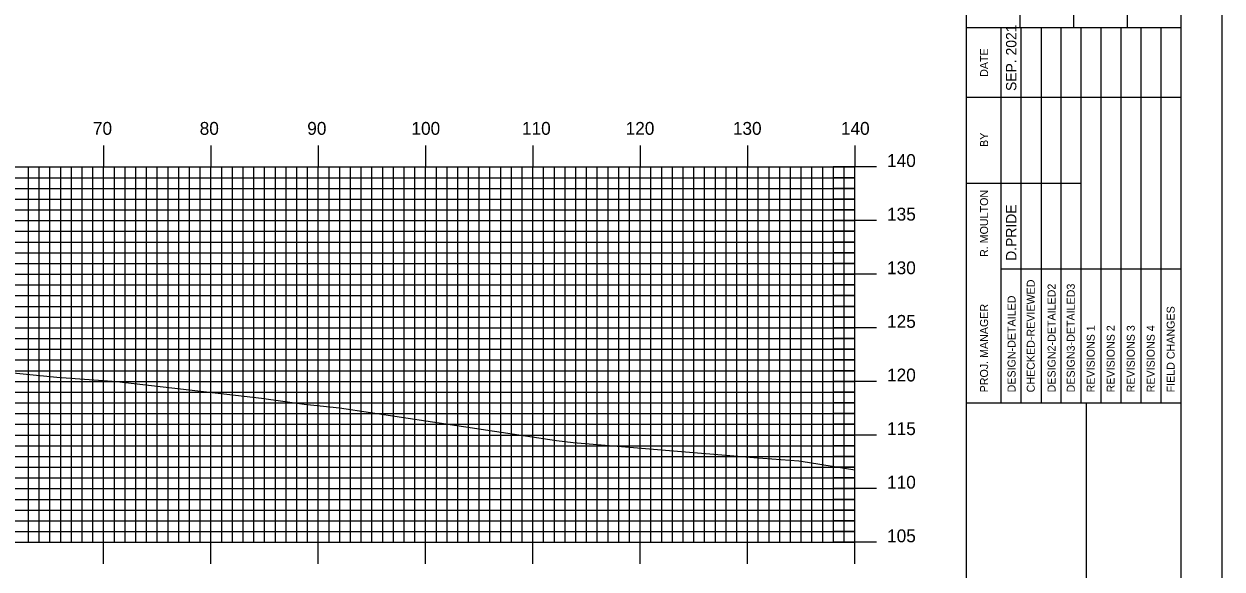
# Model space of a CAD drawing. Extents: x 1785402 to 1785745, y 442591 to 442811.
# Drawn here: x 1785630.1 to 1785741.8, y 442671.2 to 442722 of the extents above; entities that cross this region are included whole.
import ezdxf

# ---------------------------------------------------------------- set-up
doc = ezdxf.new("R2010")
doc.units = 0
for name, color, linetype in [('BORDER', 7, 'Continuous'), ('H_V ANNOTATION', 7, 'Continuous'), ('MAJOR', 7, 'Continuous'), ('MINOR', 7, 'Continuous'), ('PLOT BOUNDARY', 7, 'Continuous'), ('S_Roadway_Centerline', 7, 'Continuous')]:
    doc.layers.add(name, color=color, linetype=linetype)

msp = doc.modelspace()

# ---------------------------------------------------------------- linework, layer by layer
at = {"layer": 'BORDER'}
for p, q in [((1785717.94, 442596.67), (1785717.94, 442806.67)), ((1785722.94, 442721.67), (1785722.94, 442738.97)), ((1785722.94, 442721.67), (1785722.94, 442738.97)), ((1785727.94, 442721.67), (1785727.94, 442738.97)), ((1785727.94, 442721.67), (1785727.94, 442738.97)), ((1785732.94, 442721.67), (1785732.94, 442738.97)), ((1785732.94, 442721.67), (1785732.94, 442738.97)), ((1785717.94, 442721.67), (1785737.94, 442721.67)), ((1785717.94, 442721.67), (1785737.94, 442721.67)), ((1785717.94, 442686.67), (1785737.94, 442686.67)), ((1785717.94, 442686.67), (1785737.94, 442686.67)), ((1785729.12, 442616.67), (1785729.12, 442686.67)), ((1785729.12, 442616.67), (1785729.12, 442686.67))]:
    msp.add_line(p, q, dxfattribs=at)
msp.add_lwpolyline([(1785417.94, 442596.67), (1785737.94, 442596.67), (1785737.94, 442806.67), (1785417.94, 442806.67)], close=True, dxfattribs=at)
for points in [[(1785721.17, 442715.17), (1785721.17, 442721.67)], [(1785721.17, 442715.17), (1785721.17, 442721.67)], [(1785723.03, 442686.68), (1785723.03, 442721.67)], [(1785723.03, 442686.68), (1785723.03, 442721.67)], [(1785724.9, 442721.67), (1785724.9, 442686.68)], [(1785724.9, 442721.67), (1785724.9, 442686.68)], [(1785726.76, 442686.68), (1785726.76, 442721.67)], [(1785726.76, 442686.68), (1785726.76, 442721.67)], [(1785728.62, 442686.68), (1785728.62, 442721.67)], [(1785728.62, 442686.68), (1785728.62, 442721.67)], [(1785730.49, 442686.68), (1785730.49, 442721.67)], [(1785730.49, 442686.68), (1785730.49, 442721.67)], [(1785732.35, 442686.68), (1785732.35, 442721.67)], [(1785732.35, 442686.68), (1785732.35, 442721.67)], [(1785734.21, 442686.68), (1785734.21, 442721.67)], [(1785734.21, 442686.68), (1785734.21, 442721.67)], [(1785736.08, 442686.68), (1785736.08, 442721.67)], [(1785736.08, 442686.68), (1785736.08, 442721.67)], [(1785721.17, 442686.68), (1785721.17, 442720.26)], [(1785721.17, 442686.68), (1785721.17, 442720.26)], [(1785717.94, 442715.17), (1785737.94, 442715.17)], [(1785717.94, 442715.17), (1785737.94, 442715.17)], [(1785717.94, 442707.17), (1785721.17, 442707.17)], [(1785717.94, 442707.17), (1785721.17, 442707.17)], [(1785721.17, 442707.17), (1785728.62, 442707.17)], [(1785721.17, 442707.17), (1785728.62, 442707.17)], [(1785721.17, 442699.17), (1785737.94, 442699.17)], [(1785721.17, 442699.17), (1785737.94, 442699.17)]]:
    msp.add_lwpolyline(points, dxfattribs=at)
at = {"layer": 'MAJOR'}
for p, q in [((1785637.54, 442710.67), (1785637.54, 442708.67)), ((1785647.54, 442710.67), (1785647.54, 442708.67)), ((1785657.54, 442710.67), (1785657.54, 442708.67)), ((1785667.54, 442710.67), (1785667.54, 442708.67)), ((1785677.54, 442710.67), (1785677.54, 442708.67)), ((1785687.54, 442710.67), (1785687.54, 442708.67)), ((1785697.54, 442710.67), (1785697.54, 442708.67)), ((1785707.54, 442710.67), (1785707.54, 442708.67)), ((1785427.54, 442708.67), (1785707.54, 442708.67)), ((1785427.54, 442708.67), (1785707.54, 442708.67)), ((1785637.54, 442673.67), (1785637.54, 442708.67)), ((1785647.54, 442673.67), (1785647.54, 442708.67)), ((1785657.54, 442673.67), (1785657.54, 442708.67)), ((1785667.54, 442673.67), (1785667.54, 442708.67)), ((1785677.54, 442673.67), (1785677.54, 442708.67)), ((1785687.54, 442673.67), (1785687.54, 442708.67)), ((1785697.54, 442673.67), (1785697.54, 442708.67)), ((1785709.54, 442708.67), (1785705.53, 442708.67)), ((1785707.54, 442673.67), (1785707.54, 442708.67)), ((1785707.54, 442673.67), (1785707.54, 442708.67)), ((1785427.54, 442703.67), (1785707.54, 442703.67)), ((1785709.54, 442703.67), (1785705.53, 442703.67)), ((1785427.54, 442698.67), (1785707.54, 442698.67)), ((1785709.54, 442698.67), (1785705.53, 442698.67)), ((1785427.54, 442693.67), (1785707.54, 442693.67)), ((1785709.54, 442693.67), (1785705.53, 442693.67)), ((1785427.54, 442688.67), (1785707.54, 442688.67)), ((1785709.54, 442688.67), (1785705.53, 442688.67)), ((1785427.54, 442683.67), (1785707.54, 442683.67)), ((1785709.54, 442683.67), (1785705.53, 442683.67)), ((1785427.54, 442678.67), (1785707.54, 442678.67)), ((1785709.54, 442678.67), (1785705.53, 442678.67)), ((1785427.54, 442673.67), (1785707.54, 442673.67)), ((1785427.54, 442673.67), (1785707.54, 442673.67)), ((1785637.54, 442671.66), (1785637.54, 442673.67)), ((1785647.54, 442671.66), (1785647.54, 442673.67)), ((1785657.54, 442671.66), (1785657.54, 442673.67)), ((1785667.54, 442671.66), (1785667.54, 442673.67)), ((1785677.54, 442671.66), (1785677.54, 442673.67)), ((1785687.54, 442671.66), (1785687.54, 442673.67)), ((1785697.54, 442671.66), (1785697.54, 442673.67)), ((1785709.54, 442673.67), (1785705.53, 442673.67)), ((1785707.54, 442671.66), (1785707.54, 442673.67))]:
    msp.add_line(p, q, dxfattribs=at)
at = {"layer": 'MINOR'}
for p, q in [((1785630.54, 442673.67), (1785630.54, 442708.67)), ((1785631.54, 442673.67), (1785631.54, 442708.67)), ((1785632.54, 442673.67), (1785632.54, 442708.67)), ((1785633.54, 442673.67), (1785633.54, 442708.67)), ((1785634.54, 442673.67), (1785634.54, 442708.67)), ((1785635.54, 442673.67), (1785635.54, 442708.67)), ((1785636.54, 442673.67), (1785636.54, 442708.67)), ((1785638.54, 442673.67), (1785638.54, 442708.67)), ((1785639.54, 442673.67), (1785639.54, 442708.67)), ((1785640.54, 442673.67), (1785640.54, 442708.67)), ((1785641.54, 442673.67), (1785641.54, 442708.67)), ((1785642.54, 442673.67), (1785642.54, 442708.67)), ((1785643.54, 442673.67), (1785643.54, 442708.67)), ((1785644.54, 442673.67), (1785644.54, 442708.67)), ((1785645.54, 442673.67), (1785645.54, 442708.67)), ((1785646.54, 442673.67), (1785646.54, 442708.67)), ((1785648.54, 442673.67), (1785648.54, 442708.67)), ((1785649.54, 442673.67), (1785649.54, 442708.67)), ((1785650.54, 442673.67), (1785650.54, 442708.67)), ((1785651.54, 442673.67), (1785651.54, 442708.67)), ((1785652.54, 442673.67), (1785652.54, 442708.67)), ((1785653.54, 442673.67), (1785653.54, 442708.67)), ((1785654.54, 442673.67), (1785654.54, 442708.67)), ((1785655.54, 442673.67), (1785655.54, 442708.67)), ((1785656.54, 442673.67), (1785656.54, 442708.67)), ((1785658.54, 442673.67), (1785658.54, 442708.67)), ((1785659.54, 442673.67), (1785659.54, 442708.67)), ((1785660.54, 442673.67), (1785660.54, 442708.67)), ((1785661.54, 442673.67), (1785661.54, 442708.67)), ((1785662.54, 442673.67), (1785662.54, 442708.67)), ((1785663.54, 442673.67), (1785663.54, 442708.67)), ((1785664.54, 442673.67), (1785664.54, 442708.67)), ((1785665.54, 442673.67), (1785665.54, 442708.67)), ((1785666.54, 442673.67), (1785666.54, 442708.67)), ((1785668.54, 442673.67), (1785668.54, 442708.67)), ((1785669.54, 442673.67), (1785669.54, 442708.67)), ((1785670.54, 442673.67), (1785670.54, 442708.67)), ((1785671.54, 442673.67), (1785671.54, 442708.67)), ((1785672.54, 442673.67), (1785672.54, 442708.67)), ((1785673.54, 442673.67), (1785673.54, 442708.67)), ((1785674.54, 442673.67), (1785674.54, 442708.67)), ((1785675.54, 442673.67), (1785675.54, 442708.67)), ((1785676.54, 442673.67), (1785676.54, 442708.67)), ((1785678.54, 442673.67), (1785678.54, 442708.67)), ((1785679.54, 442673.67), (1785679.54, 442708.67)), ((1785680.54, 442673.67), (1785680.54, 442708.67)), ((1785681.54, 442673.67), (1785681.54, 442708.67)), ((1785682.54, 442673.67), (1785682.54, 442708.67)), ((1785683.54, 442673.67), (1785683.54, 442708.67)), ((1785684.54, 442673.67), (1785684.54, 442708.67)), ((1785685.54, 442673.67), (1785685.54, 442708.67)), ((1785686.54, 442673.67), (1785686.54, 442708.67)), ((1785688.54, 442673.67), (1785688.54, 442708.67)), ((1785689.54, 442673.67), (1785689.54, 442708.67)), ((1785690.54, 442673.67), (1785690.54, 442708.67)), ((1785691.54, 442673.67), (1785691.54, 442708.67)), ((1785692.54, 442673.67), (1785692.54, 442708.67)), ((1785693.54, 442673.67), (1785693.54, 442708.67)), ((1785694.54, 442673.67), (1785694.54, 442708.67)), ((1785695.54, 442673.67), (1785695.54, 442708.67)), ((1785696.54, 442673.67), (1785696.54, 442708.67)), ((1785698.54, 442673.67), (1785698.54, 442708.67)), ((1785699.54, 442673.67), (1785699.54, 442708.67)), ((1785700.54, 442673.67), (1785700.54, 442708.67)), ((1785701.54, 442673.67), (1785701.54, 442708.67)), ((1785702.54, 442673.67), (1785702.54, 442708.67)), ((1785703.54, 442673.67), (1785703.54, 442708.67)), ((1785704.54, 442673.67), (1785704.54, 442708.67)), ((1785705.54, 442673.67), (1785705.54, 442708.67)), ((1785706.54, 442673.67), (1785706.54, 442708.67)), ((1785427.54, 442707.67), (1785707.54, 442707.67)), ((1785427.54, 442706.67), (1785707.54, 442706.67)), ((1785707.54, 442707.67), (1785705.53, 442707.67)), ((1785707.54, 442706.67), (1785705.53, 442706.67)), ((1785427.54, 442705.67), (1785707.54, 442705.67)), ((1785707.54, 442705.67), (1785705.53, 442705.67)), ((1785427.54, 442704.67), (1785707.54, 442704.67)), ((1785707.54, 442704.67), (1785705.53, 442704.67)), ((1785427.54, 442702.67), (1785707.54, 442702.67)), ((1785707.54, 442702.67), (1785705.53, 442702.67)), ((1785427.54, 442701.67), (1785707.54, 442701.67)), ((1785707.54, 442701.67), (1785705.53, 442701.67)), ((1785427.54, 442700.67), (1785707.54, 442700.67)), ((1785707.54, 442700.67), (1785705.53, 442700.67)), ((1785427.54, 442699.67), (1785707.54, 442699.67)), ((1785707.54, 442699.67), (1785705.53, 442699.67)), ((1785427.54, 442697.67), (1785707.54, 442697.67)), ((1785707.54, 442697.67), (1785705.53, 442697.67)), ((1785427.54, 442696.67), (1785707.54, 442696.67)), ((1785707.54, 442696.67), (1785705.53, 442696.67)), ((1785427.54, 442695.67), (1785707.54, 442695.67)), ((1785707.54, 442695.67), (1785705.53, 442695.67)), ((1785427.54, 442694.67), (1785707.54, 442694.67)), ((1785707.54, 442694.67), (1785705.53, 442694.67)), ((1785427.54, 442692.67), (1785707.54, 442692.67)), ((1785707.54, 442692.67), (1785705.53, 442692.67)), ((1785427.54, 442691.67), (1785707.54, 442691.67)), ((1785707.54, 442691.67), (1785705.53, 442691.67)), ((1785427.54, 442690.67), (1785707.54, 442690.67)), ((1785707.54, 442690.67), (1785705.53, 442690.67)), ((1785427.54, 442689.67), (1785707.54, 442689.67)), ((1785707.54, 442689.67), (1785705.53, 442689.67)), ((1785427.54, 442687.67), (1785707.54, 442687.67)), ((1785707.54, 442687.67), (1785705.53, 442687.67)), ((1785427.54, 442686.67), (1785707.54, 442686.67)), ((1785707.54, 442686.67), (1785705.53, 442686.67)), ((1785427.54, 442685.67), (1785707.54, 442685.67)), ((1785707.54, 442685.67), (1785705.53, 442685.67)), ((1785427.54, 442684.67), (1785707.54, 442684.67)), ((1785707.54, 442684.67), (1785705.53, 442684.67)), ((1785427.54, 442682.67), (1785707.54, 442682.67)), ((1785707.54, 442682.67), (1785705.53, 442682.67)), ((1785427.54, 442681.67), (1785707.54, 442681.67)), ((1785707.54, 442681.67), (1785705.53, 442681.67)), ((1785427.54, 442680.67), (1785707.54, 442680.67)), ((1785707.54, 442680.67), (1785705.53, 442680.67)), ((1785427.54, 442679.67), (1785707.54, 442679.67)), ((1785707.54, 442679.67), (1785705.53, 442679.67)), ((1785427.54, 442677.67), (1785707.54, 442677.67)), ((1785707.54, 442677.67), (1785705.53, 442677.67)), ((1785427.54, 442676.67), (1785707.54, 442676.67)), ((1785707.54, 442676.67), (1785705.53, 442676.67)), ((1785427.54, 442675.67), (1785707.54, 442675.67)), ((1785707.54, 442675.67), (1785705.53, 442675.67)), ((1785427.54, 442674.67), (1785707.54, 442674.67)), ((1785707.54, 442674.67), (1785705.53, 442674.67))]:
    msp.add_line(p, q, dxfattribs=at)
at = {"layer": 'PLOT BOUNDARY'}
msp.add_lwpolyline([(1785401.75, 442590.55), (1785741.75, 442590.55), (1785741.75, 442810.55), (1785401.75, 442810.55)], close=True, dxfattribs=at)
at = {"layer": 'S_Roadway_Centerline'}
msp.add_lwpolyline([(1785616.82, 442690.7), (1785633.18, 442689.06), (1785638.76, 442688.67), (1785652.25, 442687.11), (1785656.21, 442686.54), (1785659.53, 442686.21), (1785679.75, 442683.15), (1785681.28, 442682.97), (1785698.13, 442681.59), (1785702.32, 442681.26), (1785703.32, 442681.1), (1785707.54, 442680.43)], dxfattribs=at)

# ---------------------------------------------------------------- texts
at = {"layer": 'BORDER'}
for s, height, p in [('SEP. 2021', 0.969, (1785722.59, 442715.76)), ('DATE', 0.743, (1785719.95, 442717.08)), ('DATE', 0.743, (1785719.95, 442717.08)), ('BY', 0.743, (1785719.95, 442710.54)), ('BY', 0.743, (1785719.95, 442710.54)), ('R. MOULTON', 0.745, (1785719.95, 442700.28)), ('D.PRIDE', 0.969, (1785722.59, 442699.92)), ('CHECKED-REVIEWED', 0.7455, (1785724.3, 442687.65)), ('CHECKED-REVIEWED', 0.7455, (1785724.3, 442687.65)), ('DESIGN2-DETAILED2', 0.7455, (1785726.24, 442687.65)), ('DESIGN2-DETAILED2', 0.7455, (1785726.24, 442687.65)), ('DESIGN3-DETAILED3', 0.7455, (1785728.03, 442687.65)), ('DESIGN3-DETAILED3', 0.7455, (1785728.03, 442687.65)), ('DESIGN-DETAILED', 0.7455, (1785722.51, 442687.65)), ('DESIGN-DETAILED', 0.7455, (1785722.51, 442687.65)), ('PROJ. MANAGER', 0.7455, (1785719.95, 442687.65)), ('PROJ. MANAGER', 0.7455, (1785719.95, 442687.65)), ('FIELD CHANGES', 0.7455, (1785737.34, 442687.65)), ('FIELD CHANGES', 0.7455, (1785737.34, 442687.65)), ('REVISIONS 1', 0.7455, (1785729.89, 442687.65)), ('REVISIONS 1', 0.7455, (1785729.89, 442687.65)), ('REVISIONS 2', 0.7455, (1785731.75, 442687.65)), ('REVISIONS 2', 0.7455, (1785731.75, 442687.65)), ('REVISIONS 3', 0.7455, (1785733.62, 442687.65)), ('REVISIONS 3', 0.7455, (1785733.62, 442687.65)), ('REVISIONS 4', 0.7455, (1785735.48, 442687.65)), ('REVISIONS 4', 0.7455, (1785735.48, 442687.65))]:
    msp.add_text(s, height=height, rotation=90, dxfattribs=at).set_placement(p)
at = {"layer": 'H_V ANNOTATION'}
for s, p in [('70', (1785636.54, 442711.67)), ('80', (1785646.49, 442711.67)), ('90', (1785656.51, 442711.67)), ('100', (1785666.22, 442711.67)), ('110', (1785676.52, 442711.67)), ('120', (1785686.18, 442711.67)), ('130', (1785696.17, 442711.67)), ('140', (1785706.24, 442711.67)), ('140', (1785710.54, 442708.67)), ('135', (1785710.54, 442703.67)), ('130', (1785710.54, 442698.67)), ('125', (1785710.54, 442693.67)), ('120', (1785710.54, 442688.67)), ('115', (1785710.54, 442683.67)), ('110', (1785710.54, 442678.67)), ('105', (1785710.54, 442673.67))]:
    msp.add_text(s, height=1.2, dxfattribs=at).set_placement(p)

doc.saveas('drawing.dxf')
